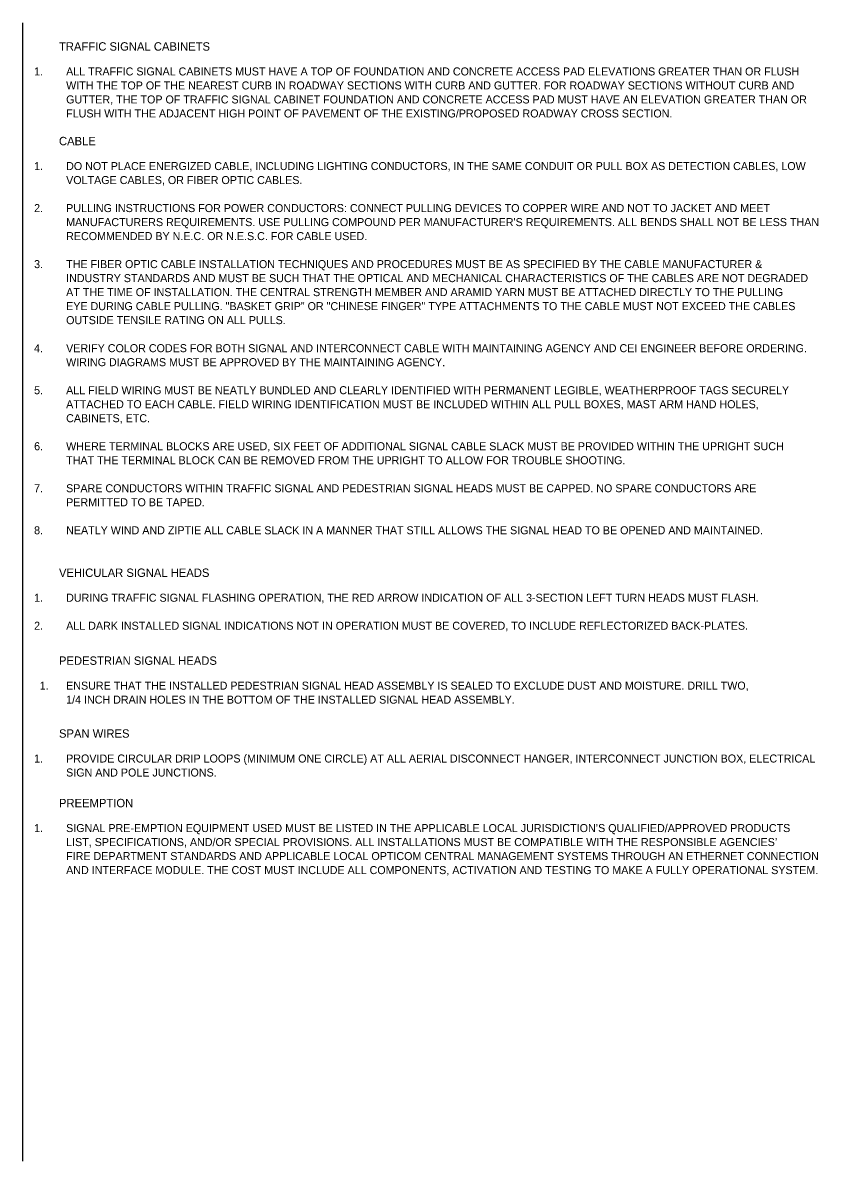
# Model space of a CAD drawing. Extents: x 2479946 to 2483081, y 3677527 to 3681234.
# Drawn here: x 2480771 to 2481441, y 3678954 to 3679914 of the extents above; entities that cross this region are included whole.
import ezdxf

# ---------------------------------------------------------------- set-up
doc = ezdxf.new("R2010")
doc.units = 0
doc.layers.add('40', color=7, linetype='Continuous')
doc.layers.add('ActivePointCell_dp', color=7, linetype='Continuous')

msp = doc.modelspace()

# ---------------------------------------------------------------- linework, layer by layer
at = {"layer": 'ActivePointCell_dp'}
msp.add_line((2480770.93, 3678954.2), (2480770.93, 3679914.2), dxfattribs=at)

# ---------------------------------------------------------------- texts
at = {"layer": '40'}
for s, height, p in [('TRAFFIC SIGNAL CABINETS', 7.08, (2480801.44, 3679890.69)), ('1.', 6.75, (2480780.48, 3679869.78)), ('ALL TRAFFIC SIGNAL CABINETS MUST HAVE A TOP OF FOUNDATION AND CONCRETE ACCESS PAD ELEVATIONS GREATER THAN OR FLUSH ', 6.75, (2480807.48, 3679869.78)), ('WITH THE TOP OF THE NEAREST CURB IN ROADWAY SECTIONS WITH CURB AND GUTTER. FOR ROADWAY SECTIONS WITHOUT CURB AND ', 6.75, (2480807.48, 3679857.97)), ('GUTTER, THE TOP OF TRAFFIC SIGNAL CABINET FOUNDATION AND CONCRETE ACCESS PAD MUST HAVE AN ELEVATION GREATER THAN OR ', 6.75, (2480807.48, 3679846.16)), ('FLUSH WITH THE ADJACENT HIGH POINT OF PAVEMENT OF THE EXISTING/PROPOSED ROADWAY CROSS SECTION.', 6.75, (2480807.48, 3679834.35)), ('CABLE', 7.08, (2480801.44, 3679810.9)), ('1.', 6.75, (2480780.48, 3679789.99)), ('DO NOT PLACE ENERGIZED CABLE, INCLUDING LIGHTING CONDUCTORS, IN THE SAME CONDUIT OR PULL BOX AS DETECTION CABLES, LOW ', 6.75, (2480807.48, 3679789.99)), ('VOLTAGE CABLES, OR FIBER OPTIC CABLES.', 6.75, (2480807.48, 3679778.18)), ('2.', 6.75, (2480780.48, 3679754.56)), ('PULLING INSTRUCTIONS FOR POWER CONDUCTORS: CONNECT PULLING DEVICES TO COPPER WIRE AND NOT TO JACKET AND MEET ', 6.75, (2480807.48, 3679754.56)), ("MANUFACTURERS REQUIREMENTS. USE PULLING COMPOUND PER MANUFACTURER'S REQUIREMENTS. ALL BENDS SHALL NOT BE LESS THAN ", 6.75, (2480807.48, 3679742.74)), ('RECOMMENDED BY N.E.C. OR N.E.S.C. FOR CABLE USED.', 6.75, (2480807.48, 3679730.93)), ('3.', 6.75, (2480780.48, 3679707.31)), ('THE FIBER OPTIC CABLE INSTALLATION TECHNIQUES AND PROCEDURES MUST BE AS SPECIFIED BY THE CABLE MANUFACTURER & ', 6.75, (2480807.48, 3679707.31)), ('INDUSTRY STANDARDS AND MUST BE SUCH THAT THE OPTICAL AND MECHANICAL CHARACTERISTICS OF THE CABLES ARE NOT DEGRADED ', 6.75, (2480807.48, 3679695.49)), ('AT THE TIME OF INSTALLATION. THE CENTRAL STRENGTH MEMBER AND ARAMID YARN MUST BE ATTACHED DIRECTLY TO THE PULLING ', 6.75, (2480807.48, 3679683.68)), ('EYE DURING CABLE PULLING. "BASKET GRIP" OR "CHINESE FINGER" TYPE ATTACHMENTS TO THE CABLE MUST NOT EXCEED THE CABLES ', 6.75, (2480807.48, 3679671.87)), ('OUTSIDE TENSILE RATING ON ALL PULLS.', 6.75, (2480807.48, 3679660.06)), ('4.', 6.75, (2480780.48, 3679636.43)), ('VERIFY COLOR CODES FOR BOTH SIGNAL AND INTERCONNECT CABLE WITH MAINTAINING AGENCY AND CEI ENGINEER BEFORE ORDERING. ', 6.75, (2480807.48, 3679636.43)), ('WIRING DIAGRAMS MUST BE APPROVED BY THE MAINTAINING AGENCY.', 6.75, (2480807.48, 3679624.62)), ('5.', 6.75, (2480780.48, 3679600.99)), ('ALL FIELD WIRING MUST BE NEATLY BUNDLED AND CLEARLY IDENTIFIED WITH PERMANENT LEGIBLE, WEATHERPROOF TAGS SECURELY ', 6.75, (2480807.48, 3679600.99)), ('ATTACHED TO EACH CABLE. FIELD WIRING IDENTIFICATION MUST BE INCLUDED WITHIN ALL PULL BOXES, MAST ARM HAND HOLES, ', 6.75, (2480807.48, 3679589.18)), ('CABINETS, ETC.', 6.75, (2480807.48, 3679577.37)), ('6.', 6.75, (2480780.48, 3679553.74)), ('WHERE TERMINAL BLOCKS ARE USED, SIX FEET OF ADDITIONAL SIGNAL CABLE SLACK MUST BE PROVIDED WITHIN THE UPRIGHT SUCH ', 6.75, (2480807.48, 3679553.74)), ('THAT THE TERMINAL BLOCK CAN BE REMOVED FROM THE UPRIGHT TO ALLOW FOR TROUBLE SHOOTING.', 6.75, (2480807.48, 3679541.93)), ('7.', 6.75, (2480780.48, 3679518.31)), ('SPARE CONDUCTORS WITHIN TRAFFIC SIGNAL AND PEDESTRIAN SIGNAL HEADS MUST BE CAPPED. NO SPARE CONDUCTORS ARE ', 6.75, (2480807.48, 3679518.31)), ('PERMITTED TO BE TAPED.', 6.75, (2480807.48, 3679506.49)), ('8.', 6.75, (2480780.48, 3679482.87)), ('NEATLY WIND AND ZIPTIE ALL CABLE SLACK IN A MANNER THAT STILL ALLOWS THE SIGNAL HEAD TO BE OPENED AND MAINTAINED.', 6.75, (2480807.48, 3679482.87)), ('VEHICULAR SIGNAL HEADS', 7.08, (2480801.44, 3679446.9)), ('1.', 6.75, (2480780.48, 3679425.99)), ('DURING TRAFFIC SIGNAL FLASHING OPERATION, THE RED ARROW INDICATION OF ALL 3-SECTION LEFT TURN HEADS MUST FLASH. ', 6.75, (2480807.48, 3679425.99)), ('2.', 6.75, (2480780.48, 3679402.37)), ('ALL DARK INSTALLED SIGNAL INDICATIONS NOT IN OPERATION MUST BE COVERED, TO INCLUDE REFLECTORIZED BACK-PLATES.', 6.75, (2480807.48, 3679402.37)), ('PEDESTRIAN SIGNAL HEADS', 7.08, (2480801.44, 3679372.79)), ('1.', 6.75, (2480785.21, 3679351.88)), ('ENSURE THAT THE INSTALLED PEDESTRIAN SIGNAL HEAD ASSEMBLY IS SEALED TO EXCLUDE DUST AND MOISTURE. DRILL TWO, ', 6.75, (2480807.48, 3679351.88)), ('1/4 INCH DRAIN HOLES IN THE BOTTOM OF THE INSTALLED SIGNAL HEAD ASSEMBLY.', 6.75, (2480807.48, 3679340.06)), ('SPAN WIRES', 7.08, (2480801.44, 3679311.33)), ('1.', 6.75, (2480780.48, 3679290.42)), ('PROVIDE CIRCULAR DRIP LOOPS (MINIMUM ONE CIRCLE) AT ALL AERIAL DISCONNECT HANGER, INTERCONNECT JUNCTION BOX, ELECTRICAL ', 6.75, (2480807.48, 3679290.42)), ('SIGN AND POLE JUNCTIONS.', 6.75, (2480807.48, 3679278.61)), ('PREEMPTION', 7.08, (2480801.44, 3679252.67)), ('1.', 6.75, (2480780.48, 3679231.76)), ('SIGNAL PRE-EMPTION EQUIPMENT USED MUST BE LISTED IN THE APPLICABLE LOCAL JURISDICTION’S QUALIFIED/APPROVED PRODUCTS ', 6.75, (2480807.48, 3679231.76)), ('LIST, SPECIFICATIONS, AND/OR SPECIAL PROVISIONS. ALL INSTALLATIONS MUST BE COMPATIBLE WITH THE RESPONSIBLE AGENCIES’ ', 6.75, (2480807.48, 3679219.95)), ('FIRE DEPARTMENT STANDARDS AND APPLICABLE LOCAL OPTICOM CENTRAL MANAGEMENT SYSTEMS THROUGH AN ETHERNET CONNECTION ', 6.75, (2480807.48, 3679208.14)), ('AND INTERFACE MODULE. THE COST MUST INCLUDE ALL COMPONENTS, ACTIVATION AND TESTING TO MAKE A FULLY OPERATIONAL SYSTEM.', 6.75, (2480807.48, 3679196.32))]:
    msp.add_text(s, height=height, dxfattribs=at).set_placement(p)

doc.saveas('drawing.dxf')
